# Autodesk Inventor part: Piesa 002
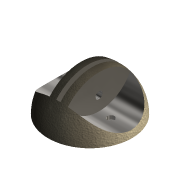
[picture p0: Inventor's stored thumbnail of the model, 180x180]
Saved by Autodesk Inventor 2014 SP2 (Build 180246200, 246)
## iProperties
Created: 2009-01
Part Number: Piesa 002
Document SubType Name: Modeling
Designer: Costel
Material: Steel
Mass: 253.801 g
Surface Area: 111.536 cm^2
Volume: 32.3313 cm^3
Density: 7.85 g/cm^3
Appearance: Steel - Polished
Author: Costel
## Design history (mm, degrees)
sketch "Sketch1"
  geometry: L1 (-36, 0)-(48, 0) reference; A1 r 30 centre (0, 0) between (30, 0) and (-30, 0)
  constraints: 2 point on circle, 2 point on line, 1 centre point
  dimensions: "d0" = 60 diameter of A1
revolve "Revolution1" sketch "Sketch1" stored, may be unused: angle "d1" = 180 deg
sketch "Sketch2"
  geometry: L1 (-6.5, 30)-(-30, 30); L2 (-30, 5)-(-30, 30); L3 (-6.5, 5)-(-30, 5); L4 (0, -3)-(0, 39) reference; L5 (0, 30)-(0, 7.282); L6 (-6.5, 5)-(-6.5, 30); L7 (-1.5, 30)-(-1.5, 5); L8 (-1.5, 5)-(0, 5); L9 (-1.5, 30)-(0, 30); L10 (1.5, 30)-(1.5, 5); L11 (6.5, 5)-(6.5, 30); L12 (30, 5)-(30, 30); L13 (6.5, 30)-(30, 30); L14 (6.5, 5)-(30, 5); L15 (1.5, 5)-(0, 5); L16 (1.5, 30)-(0, 30); A1 r 30 centre (0, 0) between (30, 0) and (-30, 0) reference
  constraints: 30 end point, 6 symmetric about line, 4 perpendicular, 3 collinear, 3 point on line, 2 tangent, 1 horizontal, 1 parallel, 1 point on circle
  dimensions: "d2" = 3 distance between parallel lines of L7 L10; "d3" = 13 distance between parallel lines of L6 L11; "d4" = 25 distance between parallel lines of L13 L14
revolve "Revolution2" sketch "Sketch2" stored, may be unused: angle "d5" = 180 deg
sketch "Sketch4"
  geometry: L1 (30, -42)-(30, 42) reference; L2 (35.992, 0)-(-5.955, 0) reference; C1 r 2.5 at (15, 0)
  constraints: 1 centre point, 1 point on line
  dimensions: "d23" = 15 distance from line of L1 C1.centre; "d24" = 5 diameter of C1
extrude "Extrusion1" cut sketch "Sketch4" stored distance "d25" = 10; taper "d26" = 0 deg
sketch "Sketch5"
  geometry: L1 (-15, 8.974)-(-17.5, 8.974); L2 (-17.5, 8.974)-(-17.5, 2.5); L3 (-17.5, 2.5)-(-16.25, 2.5); L4 (-15, 0)-(-15, 8.974); L5 (-16.25, 2.5)-(-16.25, 0); L6 (-16.25, 0)-(-15, 0); L7 (36, 0)-(-48, 0) reference; L8 (0, -2.996)-(0, 38.951) reference
  constraints: 12 end point, 2 parallel, 1 collinear, 1 horizontal, 1 perpendicular
  dimensions: "d27" = 2.5 distance of L1.start L1.end; "d28" = 1.25 distance of L5.end L4.start; "d29" = 2.5 distance between parallel lines of L6 L3; "d30" = 15 distance between parallel lines of L8 L4
revolve "Revolution3" sketch "Sketch5" stored, may be unused: angle "d31" = 90 deg
mirror "Mirror2"
body "Solid1"
